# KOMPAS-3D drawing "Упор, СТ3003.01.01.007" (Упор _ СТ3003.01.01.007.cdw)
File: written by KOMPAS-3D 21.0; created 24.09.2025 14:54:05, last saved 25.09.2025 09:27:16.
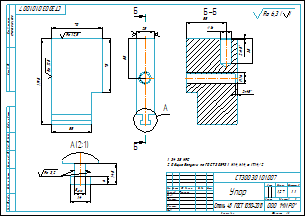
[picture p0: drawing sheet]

Sheet 1: A3, landscape

Document properties: Знак неуказанной шероховатости: 4; Параметр неуказанной шероховатости: Ra 6,3; Масса: 1.271359; Полное имя файла: ..\..\3D\Кронштейн _ СТ3003.01.01.000\Упор _ СТ.3003.01.01.007.m3d

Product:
- Part/product: Упор  | designation СТ3003.01.01.007
    Материал: Сталь 45  ГОСТ 1050-2013 (density 7810 kg/m3)
    Масса: 1.271359

Title block, sheet 1: Наименование: Упор; designation: СТ3003.01.01.007; Материал: Сталь 45  ГОСТ 1050-2013; Масса: 1,27; Количество листов документа: 1; organisation: ООО "МИРО"; Форматы листов документа: A3; stored path: C:\Users\1\Yandex.Disk\Документы\Новая папка\Стапель №2\Стапель _ СТ3003.00.00.000\Опора _ СТ3003.01.00.000\2D\Кронштейн _ СТ3003.01.01.000\Упор _ СТ3003.01.01.007.cdw; Разработал: Тимонин

Views: Вид 1, Спереди, Проекционный вид 2, Разрез А-А, Выносной элемент 4, Разрез Б-Б, Выносной элемент А, Выносной элемент
Referenced files in C:\Users\1\Yandex.Disk\Документы\Новая папка\Стапель №2\Стапель _ СТ3003.00.00.000\Опора _ СТ3003.01.00.000\3D\Кронштейн _ СТ3003.01.01.000\: Упор _ СТ.3003.01.01.007.m3d
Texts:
  Ra 12,5
  Ra 3,2
  Ra 6,3
  Ra 6,3 ( )
  СТ3003.01.01.000
  СТ3003.01.01.007 Упор
Dimensions and other numbers on the sheet: 70; 119,5; 75; 55; 25; 2; 35; 16; 8; 14; 14,5; 6; 1:1; 1; 1,27

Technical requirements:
  34...38 HRC.
  Общие допуски по ГОСТ 30893.1: Н14, h14, ± IT14/2.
